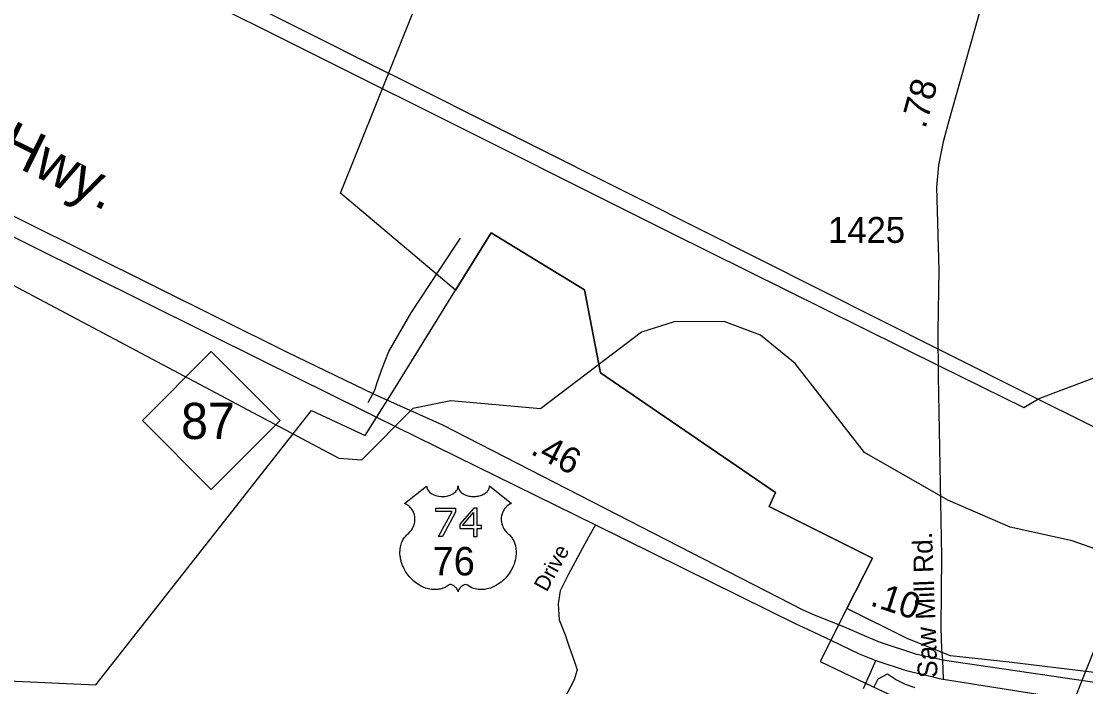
# Model space of a CAD drawing. Extents: x 2225501 to 2309677, y 165449 to 227696.
# Drawn here: x 2252503 to 2257649, y 196661 to 199877 of the extents above; entities that cross this region are included whole.
import ezdxf

# ---------------------------------------------------------------- set-up
doc = ezdxf.new("R2010")
doc.units = 0
for name, color, linetype in [('Black Area Fill Shapes', 7, 'Continuous'), ('E_RDY_CMT_EOP', 7, 'Continuous'), ('MARK ENDS WORD SYMBOL CELL', 7, 'Continuous'), ('Old_Level_3', 7, 'Continuous'), ('Old_Level_33', 7, 'Continuous'), ('Old_Level_46', 7, 'Continuous'), ('P_HYD_Ditch_Flow_Line', 7, 'Continuous'), ('P_HYD_Endwall_838_01_48_Dia_Single_CELL', 7, 'Continuous'), ('P_HYD_Junction_Box_with_Slab_Lid_840_31_15_Dia-Top_CELL', 7, 'Continuous'), ('P_HYD_RipRap_Pad_876_02_18in_Outlet_With_Ditch-Top_CELL', 7, 'Continuous'), ('P_HYD_RipRap_Pad_876_02_18in_Outlet_With_Ditch_CELL', 7, 'Continuous'), ('P_HYD_RipRap_Pad_876_02_24in_Outlet_With_Ditch_CELL', 7, 'Continuous'), ('P_HYD_RipRap_Pad_876_02_36in_Outlet_With_Ditch-Top_CELL', 7, 'Continuous'), ('P_RDY_Dimension_Text', 7, 'Continuous'), ('Prop Support', 7, 'Continuous'), ('Raster_Level_0', 7, 'Continuous'), ('Scratch_Level_2', 7, 'Continuous'), ('Typical Terminator CELL', 7, 'Continuous')]:
    doc.layers.add(name, color=color, linetype=linetype)

msp = doc.modelspace()

# ---------------------------------------------------------------- linework, layer by layer
at = {"layer": 'Black Area Fill Shapes'}
for p, q in [((2254291.9, 199620.2), (2254290.5, 199620.9)), ((2254260.8, 199546.4), (2254361.9, 199495.8)), ((2257417.6, 198050.9), (2256943.1, 198289.2))]:
    msp.add_line(p, q, dxfattribs=at)
for points in [[(2254290.5, 199620.9), (2252914.9, 200311.1), (2250919.7, 201308.6), (2250845.6, 201345.2)], [(2250805.9, 201279), (2252943.9, 200205.6), (2254260.8, 199546.4)], [(2256943.1, 198289.2), (2255486.5, 199020.7), (2254291.9, 199620.2)], [(2254361.9, 199495.8), (2255643.9, 198854.1), (2256944, 198211)], [(2259154.8, 198713.5), (2258436.2, 198435), (2257417.6, 198050.9)], [(2256944, 198211), (2257350, 198010.2), (2257417.6, 198050.9)], [(2259922.2, 196804.3), (2258742.4, 197393.8), (2257417.6, 198050.9)]]:
    msp.add_lwpolyline(points, dxfattribs=at)
at = {"layer": 'Old_Level_3'}
for p, q in [((2254525.6, 198676.1), (2254626.4, 198828.6)), ((2254180, 198034.4), (2254212.4, 198093.9)), ((2254212.4, 198093.9), (2254225.1, 198135.7)), ((2255278.5, 197442.7), (2255246, 197383.3)), ((2255246, 197383.3), (2255216.7, 197329.9)), ((2256606.8, 196725.5), (2256635.4, 196787.9)), ((2256575.3, 196652.4), (2256585.6, 196677.3))]:
    msp.add_line(p, q, dxfattribs=at)
for points in [[(2254225.1, 198135.7), (2254228, 198144.9), (2254245.4, 198191.5), (2254280.3, 198281.7), (2254387.9, 198467.9), (2254525.6, 198676.1)], [(2255216.7, 197329.9), (2255147, 197202.3), (2255108.3, 197124.9), (2255098.6, 197062), (2255103.4, 196984.6), (2255132.4, 196912), (2255151.8, 196853.9), (2255176, 196786.2), (2255190.5, 196742.7), (2255176, 196694.3), (2255127.6, 196602.3), (2255064.7, 196481.4)], [(2256585.6, 196677.3), (2256596.9, 196704.6), (2256606.8, 196725.5)]]:
    msp.add_lwpolyline(points, dxfattribs=at)
at = {"layer": 'Old_Level_33'}
for points in [[(2257406.3, 200835.2), (2257377.1, 200772.2), (2257211.9, 200191.2), (2256987.1, 199395.5), (2256959.8, 199295), (2256937.7, 199182.5), (2256927.5, 199075.2), (2256938.8, 198674.7), (2256934.3, 198380.7), (2256936, 198161.9), (2256951.6, 197291.5), (2256949.8, 196947.1), (2256952.3, 196843.1), (2256956.7, 196790)], [(2256956.7, 196790), (2256960.1, 196697.4)]]:
    msp.add_lwpolyline(points, dxfattribs=at)
at = {"layer": 'Old_Level_46'}
for points in [[(2256956.7, 196790), (2256924.7, 196796.5), (2256832.3, 196817.3), (2256652.3, 196875.8), (2256591.1, 196902.4), (2256480.1, 196951.1), (2256338.5, 197006.2), (2256282.6, 197031), (2254541.8, 197924.5), (2254210.5, 198073.2), (2253786.6, 198278.1), (2252185.6, 199073.8), (2250121.7, 200127.7), (2248768.8, 200789.1), (2247375.2, 201475.6), (2243675.2, 203270.8), (2243284.4, 203458.4), (2243017.1, 203588.4)], [(2242986.4, 203530.7), (2247394.3, 201340.7), (2248933.2, 200581.2), (2250061.9, 200025.4), (2252258.3, 198936.4), (2253668.1, 198237.8), (2254159.3, 197994.4), (2254220.9, 197964), (2255278.5, 197442.7), (2256250.7, 196963.5), (2256279.6, 196949.9), (2256416.4, 196885.1), (2256553.4, 196820.3), (2256635.4, 196787.9), (2256780.8, 196739.2), (2256905.8, 196709.8), (2256941.4, 196700.5), (2256960.1, 196697.4)], [(2260176.7, 196311.4), (2259597.7, 196392.1), (2259295.9, 196446.1), (2256956.7, 196790)], [(2256960.1, 196697.4), (2259291.8, 196328.6), (2260129, 196210.1)]]:
    msp.add_lwpolyline(points, dxfattribs=at)
at = {"layer": 'P_HYD_Ditch_Flow_Line'}
for points in [[(2254602, 197503.9), (2254539.9, 197386.9), (2254520.1, 197386.9), (2254586.1, 197508.2), (2254507.9, 197508.2), (2254507.9, 197524.4), (2254602, 197524.4)], [(2254728.1, 197425.6), (2254728.1, 197440.4), (2254707.6, 197440.4), (2254707.6, 197524.4), (2254690.6, 197524.4), (2254624, 197446.8), (2254624, 197425.6), (2254689.9, 197425.6), (2254689.9, 197386.9), (2254707.6, 197386.9), (2254707.6, 197425.6)], [(2254689.9, 197440.4), (2254636.6, 197440.4), (2254689.9, 197502.5)]]:
    msp.add_lwpolyline(points, close=True, dxfattribs=at)
at = {"layer": 'P_HYD_Endwall_838_01_48_Dia_Single_CELL'}
for points in [[(2254602.2, 198577.4), (2254045.8, 199046.2), (2254853.5, 201059.1)], [(2262842.5, 200192.5), (2261366.2, 197772.7), (2261577, 197677.7), (2260763, 196442.2), (2260802.2, 196384.7), (2260862.2, 196311.2), (2260865.8, 196276.6), (2260817.5, 196273.6), (2260687.2, 196340.6), (2260589.5, 196380.7), (2260484.8, 196410.3), (2260197, 196442.9), (2259793.2, 196485.6), (2259224.8, 196551.9), (2258394, 196652.1), (2257678.2, 196731.8), (2257280, 196779.1), (2256995.8, 196809.4), (2256790.2, 196891.6), (2256494.5, 197038.7)], [(2254602.2, 198577.4), (2254774.2, 198855.3), (2255225.8, 198578.8), (2255303, 198178.2), (2256150, 197600.3), (2256118.8, 197532.2), (2256618.2, 197283), (2256494.5, 197038.7)], [(2256494.5, 197038.7), (2256618.2, 197283), (2256118.8, 197532.2), (2256150, 197600.3), (2255303, 198178.2), (2255225.8, 198578.8), (2254774.2, 198855.3), (2254602.2, 198577.4)], [(2251977.8, 196710.8), (2252864.2, 196669.4), (2253906.2, 197995.3), (2254165.5, 197874.8), (2254302, 198092.7), (2254602.2, 198577.4)], [(2256494.5, 197038.7), (2256364.8, 196783), (2256585.5, 196677.3), (2256673, 196635.5), (2257043.5, 196469), (2257338.8, 196340.6), (2257312.8, 196291), (2257293.5, 196254.1), (2256809.5, 195327.1), (2256412.5, 194566.7), (2256138.2, 194034.5), (2255283, 194024), (2255235, 194023.4), (2255283, 194408), (2254952, 193845.2), (2254422.2, 193712.7), (2253942.2, 193812), (2253061.8, 194329), (2252072.5, 194910)]]:
    msp.add_lwpolyline(points, dxfattribs=at)
at = {"layer": 'P_HYD_Junction_Box_with_Slab_Lid_840_31_15_Dia-Top_CELL'}
for p, q in [((2253088.4, 197947.8), (2253421.4, 198280.8)), ((2253421.4, 198280.8), (2253754.4, 197947.8)), ((2253421.4, 197614.8), (2253088.4, 197947.8)), ((2253754.4, 197947.8), (2253421.4, 197614.8))]:
    msp.add_line(p, q, dxfattribs=at)
at = {"layer": 'P_HYD_RipRap_Pad_876_02_18in_Outlet_With_Ditch-Top_CELL'}
for p, q in [((2254356.5, 197546.3), (2254462.7, 197631)), ((2254462.7, 197631), (2254463, 197626.6)), ((2254463, 197626.6), (2254464.1, 197621.3)), ((2254614.4, 197625.3), (2254614.8, 197631.2)), ((2254614.8, 197631.2), (2254615.2, 197626.2)), ((2254615.2, 197626.2), (2254615.7, 197623.2)), ((2254766.3, 197624.4), (2254766.8, 197628.1)), ((2254766.8, 197628.1), (2254766.9, 197631.3)), ((2254766.9, 197631.3), (2254873.2, 197546.6)), ((2254464.1, 197621.3), (2254464.9, 197618.6)), ((2254464.9, 197618.6), (2254467.4, 197613.5)), ((2254467.4, 197613.5), (2254471.4, 197607.4)), ((2254471.4, 197607.4), (2254477, 197601.4)), ((2254477, 197601.4), (2254483.3, 197596.2)), ((2254483.3, 197596.2), (2254487.6, 197593.5)), ((2254487.6, 197593.5), (2254494.8, 197589.6)), ((2254494.8, 197589.6), (2254503.1, 197586.1)), ((2254503.1, 197586.1), (2254512.2, 197583.5)), ((2254512.2, 197583.5), (2254521.6, 197581.6)), ((2254521.6, 197581.6), (2254531.8, 197580.5)), ((2254531.8, 197580.5), (2254541.9, 197580.3)), ((2254541.9, 197580.3), (2254552.8, 197581.1)), ((2254552.8, 197581.1), (2254564.9, 197583.4)), ((2254564.9, 197583.4), (2254570.5, 197584.9)), ((2254570.5, 197584.9), (2254576.7, 197587)), ((2254576.7, 197587), (2254582.5, 197589.4)), ((2254582.5, 197589.4), (2254588.8, 197592.8)), ((2254588.8, 197592.8), (2254593.9, 197596)), ((2254593.9, 197596), (2254597.9, 197598.9)), ((2254597.9, 197598.9), (2254603.5, 197604.3)), ((2254603.5, 197604.3), (2254608, 197609.9)), ((2254608, 197609.9), (2254609.9, 197613)), ((2254609.9, 197613), (2254611.5, 197616.1)), ((2254611.5, 197616.1), (2254613.8, 197622.5)), ((2254613.8, 197622.5), (2254614.4, 197625.3)), ((2254615.7, 197623.2), (2254616.5, 197620.1)), ((2254616.5, 197620.1), (2254617.8, 197616.9)), ((2254617.8, 197616.9), (2254620, 197612.4)), ((2254620, 197612.4), (2254622.5, 197608.7)), ((2254622.5, 197608.7), (2254627.3, 197603.1)), ((2254627.3, 197603.1), (2254630.2, 197600.3)), ((2254630.2, 197600.3), (2254632.9, 197598.1)), ((2254632.9, 197598.1), (2254640.2, 197593.1)), ((2254640.2, 197593.1), (2254648.6, 197588.9)), ((2254648.6, 197588.9), (2254652.7, 197587.1)), ((2254652.7, 197587.1), (2254657, 197585.5)), ((2254657, 197585.5), (2254662.4, 197583.9)), ((2254662.4, 197583.9), (2254668, 197582.6)), ((2254668, 197582.6), (2254673.5, 197581.6)), ((2254673.5, 197581.6), (2254679.2, 197580.8)), ((2254679.2, 197580.8), (2254684.9, 197580.4)), ((2254684.9, 197580.4), (2254689.6, 197580.3)), ((2254689.6, 197580.3), (2254695.4, 197580.3)), ((2254695.4, 197580.3), (2254700.8, 197580.6)), ((2254700.8, 197580.6), (2254706.2, 197581.3)), ((2254706.2, 197581.3), (2254712.2, 197582.3)), ((2254712.2, 197582.3), (2254717.1, 197583.3)), ((2254717.1, 197583.3), (2254723.5, 197585)), ((2254723.5, 197585), (2254729.3, 197587.1)), ((2254729.3, 197587.1), (2254734.3, 197589.3)), ((2254734.3, 197589.3), (2254740.9, 197592.8)), ((2254740.9, 197592.8), (2254746.3, 197596.1)), ((2254746.3, 197596.1), (2254750.2, 197599.2)), ((2254750.2, 197599.2), (2254754.8, 197603.5)), ((2254754.8, 197603.5), (2254759.2, 197608.6)), ((2254759.2, 197608.6), (2254761.8, 197612.3)), ((2254761.8, 197612.3), (2254763.6, 197616.1)), ((2254763.6, 197616.1), (2254765.3, 197620.1)), ((2254765.3, 197620.1), (2254766.3, 197624.4)), ((2254359.8, 197545), (2254356.5, 197546.3)), ((2254365, 197542.4), (2254359.8, 197545)), ((2254370.4, 197539.1), (2254365, 197542.4)), ((2254374.7, 197536.1), (2254370.4, 197539.1)), ((2254379.2, 197532.5), (2254374.7, 197536.1)), ((2254383.9, 197527.8), (2254379.2, 197532.5)), ((2254388.6, 197522.6), (2254383.9, 197527.8)), ((2254841.3, 197523.1), (2254838.2, 197518.8)), ((2254843.9, 197526.1), (2254841.3, 197523.1)), ((2254846.8, 197529.2), (2254843.9, 197526.1)), ((2254849.9, 197532.2), (2254846.8, 197529.2)), ((2254853, 197535), (2254849.9, 197532.2)), ((2254860.3, 197540.1), (2254853, 197535)), ((2254864.9, 197542.8), (2254860.3, 197540.1)), ((2254870.7, 197545.7), (2254864.9, 197542.8)), ((2254873.2, 197546.6), (2254870.7, 197545.7)), ((2254393.1, 197516.1), (2254388.6, 197522.6)), ((2254397.2, 197509.1), (2254393.1, 197516.1)), ((2254399.6, 197504), (2254397.2, 197509.1)), ((2254402.2, 197496.9), (2254399.6, 197504)), ((2254403.9, 197490.8), (2254402.2, 197496.9)), ((2254405.3, 197483.7), (2254403.9, 197490.8)), ((2254406.1, 197476.4), (2254405.3, 197483.7)), ((2254406.3, 197470.1), (2254406.1, 197476.4)), ((2254823.7, 197477.8), (2254823.4, 197473.3)), ((2254823.4, 197473.3), (2254823.4, 197468.8)), ((2254825, 197487.3), (2254823.7, 197477.8)), ((2254826, 197491.8), (2254825, 197487.3)), ((2254827.5, 197497.2), (2254826, 197491.8)), ((2254830.8, 197505.8), (2254827.5, 197497.2)), ((2254832.8, 197509.9), (2254830.8, 197505.8)), ((2254835.5, 197514.6), (2254832.8, 197509.9)), ((2254838.2, 197518.8), (2254835.5, 197514.6)), ((2254389.5, 197418), (2254392.6, 197422.7)), ((2254392.6, 197422.7), (2254395, 197426.9)), ((2254395, 197426.9), (2254398.3, 197433.1)), ((2254398.3, 197433.1), (2254400.2, 197437.8)), ((2254400.2, 197437.8), (2254402.7, 197444.9)), ((2254402.7, 197444.9), (2254403.9, 197450)), ((2254403.9, 197450), (2254405.1, 197456.4)), ((2254405.1, 197456.4), (2254405.9, 197462.5)), ((2254405.9, 197462.5), (2254406.3, 197470.1)), ((2254823.4, 197468.8), (2254823.7, 197464.1)), ((2254823.7, 197464.1), (2254824.1, 197459.6)), ((2254824.1, 197459.6), (2254824.9, 197454.9)), ((2254824.9, 197454.9), (2254825.7, 197450.7)), ((2254825.7, 197450.7), (2254827, 197445.6)), ((2254827, 197445.6), (2254828.9, 197439.7)), ((2254828.9, 197439.7), (2254831.2, 197434)), ((2254831.2, 197434), (2254836, 197424.8)), ((2254836, 197424.8), (2254842.3, 197415.4)), ((2254344.8, 197363.2), (2254348.3, 197370.3)), ((2254348.3, 197370.3), (2254351.7, 197376.1)), ((2254351.7, 197376.1), (2254355.9, 197382.4)), ((2254355.9, 197382.4), (2254360, 197387.7)), ((2254360, 197387.7), (2254365.5, 197393.6)), ((2254365.5, 197393.6), (2254371.1, 197399)), ((2254371.1, 197399), (2254376.3, 197403.2)), ((2254376.3, 197403.2), (2254382.4, 197409.3)), ((2254382.4, 197409.3), (2254385.6, 197412.9)), ((2254385.6, 197412.9), (2254389.5, 197418)), ((2254842.3, 197415.4), (2254846.7, 197410.1)), ((2254846.7, 197410.1), (2254851.1, 197405.6)), ((2254851.1, 197405.6), (2254857.7, 197400)), ((2254857.7, 197400), (2254861.2, 197396.9)), ((2254861.2, 197396.9), (2254865.3, 197392.8)), ((2254865.3, 197392.8), (2254872, 197385.1)), ((2254872, 197385.1), (2254874.7, 197381.4)), ((2254874.7, 197381.4), (2254877.4, 197377.4)), ((2254877.4, 197377.4), (2254879.9, 197373.2)), ((2254879.9, 197373.2), (2254882.4, 197368.6)), ((2254882.4, 197368.6), (2254884.4, 197364.7)), ((2254333.9, 197311.8), (2254334.1, 197319)), ((2254334.1, 197319), (2254334.9, 197327.3)), ((2254334.9, 197327.3), (2254336.3, 197336.2)), ((2254336.3, 197336.2), (2254338, 197343.8)), ((2254338, 197343.8), (2254339.6, 197349.2)), ((2254339.6, 197349.2), (2254341.8, 197355.9)), ((2254341.8, 197355.9), (2254344.8, 197363.2)), ((2254884.4, 197364.7), (2254888.2, 197355.6)), ((2254888.2, 197355.6), (2254890.9, 197346.7)), ((2254890.9, 197346.7), (2254892.2, 197342.1)), ((2254892.2, 197342.1), (2254894.1, 197331.6)), ((2254894.1, 197331.6), (2254894.9, 197326.5)), ((2254894.9, 197326.5), (2254895.7, 197316.3)), ((2254334, 197303.2), (2254333.9, 197311.8)), ((2254334.7, 197293.8), (2254334, 197303.2)), ((2254335.9, 197285), (2254334.7, 197293.8)), ((2254337.1, 197278.5), (2254335.9, 197285)), ((2254339.1, 197269.4), (2254337.1, 197278.5)), ((2254340.5, 197264.2), (2254339.1, 197269.4)), ((2254890.8, 197270.5), (2254888, 197261.1)), ((2254892.6, 197278.7), (2254890.8, 197270.5)), ((2254894.8, 197292.3), (2254892.6, 197278.7)), ((2254895.7, 197304), (2254894.8, 197292.3)), ((2254895.7, 197316.3), (2254895.7, 197304)), ((2254343.1, 197256), (2254340.5, 197264.2)), ((2254346.3, 197247.4), (2254343.1, 197256)), ((2254350.3, 197238), (2254346.3, 197247.4)), ((2254353.4, 197231.5), (2254350.3, 197238)), ((2254359.1, 197221.2), (2254353.4, 197231.5)), ((2254362.9, 197214.8), (2254359.1, 197221.2)), ((2254368.9, 197206.1), (2254362.9, 197214.8)), ((2254866.7, 197215.4), (2254862.3, 197208.7)), ((2254870.5, 197221.6), (2254866.7, 197215.4)), ((2254876.1, 197231.9), (2254870.5, 197221.6)), ((2254880.4, 197240.7), (2254876.1, 197231.9)), ((2254885.3, 197252.8), (2254880.4, 197240.7)), ((2254888, 197261.1), (2254885.3, 197252.8)), ((2254378.2, 197194.1), (2254368.9, 197206.1)), ((2254384.2, 197187.3), (2254378.2, 197194.1)), ((2254394.3, 197177), (2254384.2, 197187.3)), ((2254401.1, 197170.8), (2254394.3, 197177)), ((2254410.5, 197163.2), (2254401.1, 197170.8)), ((2254423, 197154.6), (2254410.5, 197163.2)), ((2254822.6, 197166.4), (2254815.5, 197161)), ((2254827.7, 197170.6), (2254822.6, 197166.4)), ((2254836, 197178), (2254827.7, 197170.6)), ((2254842.3, 197184.3), (2254836, 197178)), ((2254850.1, 197192.9), (2254842.3, 197184.3)), ((2254856.7, 197201.1), (2254850.1, 197192.9)), ((2254862.3, 197208.7), (2254856.7, 197201.1)), ((2254433.6, 197148.5), (2254423, 197154.6)), ((2254440.3, 197145.1), (2254433.6, 197148.5)), ((2254449.9, 197140.9), (2254440.3, 197145.1)), ((2254457.7, 197137.9), (2254449.9, 197140.9)), ((2254464.9, 197135.6), (2254457.7, 197137.9)), ((2254471.9, 197133.8), (2254464.9, 197135.6)), ((2254478.6, 197132.3), (2254471.9, 197133.8)), ((2254486.6, 197131.1), (2254478.6, 197132.3)), ((2254493.1, 197130.5), (2254486.6, 197131.1)), ((2254498.6, 197130.1), (2254493.1, 197130.5)), ((2254504.6, 197130), (2254498.6, 197130.1)), ((2254510.3, 197130.2), (2254504.6, 197130)), ((2254516.7, 197130.8), (2254510.3, 197130.2)), ((2254522.6, 197131.7), (2254516.7, 197130.8)), ((2254529.3, 197133), (2254522.6, 197131.7)), ((2254535.8, 197134.7), (2254529.3, 197133)), ((2254541.8, 197136.7), (2254535.8, 197134.7)), ((2254547, 197138.7), (2254541.8, 197136.7)), ((2254551.3, 197140.7), (2254547, 197138.7)), ((2254557.2, 197143.9), (2254551.3, 197140.7)), ((2254562.2, 197147), (2254557.2, 197143.9)), ((2254566.7, 197150.1), (2254562.2, 197147)), ((2254571.5, 197153.6), (2254566.7, 197150.1)), ((2254575.1, 197154.4), (2254571.5, 197153.6)), ((2254577.6, 197154.4), (2254575.1, 197154.4)), ((2254580.8, 197154.2), (2254577.6, 197154.4)), ((2254584.6, 197153.2), (2254580.8, 197154.2)), ((2254587.7, 197152), (2254584.6, 197153.2)), ((2254591.2, 197150.3), (2254587.7, 197152)), ((2254595.4, 197147.7), (2254591.2, 197150.3)), ((2254599.5, 197144.4), (2254595.4, 197147.7)), ((2254602.8, 197141.2), (2254599.5, 197144.4)), ((2254606.5, 197137), (2254602.8, 197141.2)), ((2254608.8, 197133.6), (2254606.5, 197137)), ((2254611.1, 197129.9), (2254608.8, 197133.6)), ((2254613, 197125.5), (2254611.1, 197129.9)), ((2254614.7, 197118.8), (2254613, 197125.5)), ((2254615.9, 197124.1), (2254614.7, 197118.8)), ((2254617.3, 197127.7), (2254615.9, 197124.1)), ((2254618.6, 197130.4), (2254617.3, 197127.7)), ((2254622.3, 197136.3), (2254618.6, 197130.4)), ((2254624.2, 197138.5), (2254622.3, 197136.3)), ((2254626.8, 197141.4), (2254624.2, 197138.5)), ((2254630.4, 197144.9), (2254626.8, 197141.4)), ((2254633.4, 197147.3), (2254630.4, 197144.9)), ((2254637.3, 197149.8), (2254633.4, 197147.3)), ((2254640.3, 197151.4), (2254637.3, 197149.8)), ((2254645.2, 197153.4), (2254640.3, 197151.4)), ((2254649.9, 197154.4), (2254645.2, 197153.4)), ((2254655, 197154.1), (2254649.9, 197154.4)), ((2254657.2, 197153.5), (2254655, 197154.1)), ((2254661, 197151.5), (2254657.2, 197153.5)), ((2254674.1, 197143.2), (2254661, 197151.5)), ((2254681.9, 197139.4), (2254674.1, 197143.2)), ((2254689.6, 197136.4), (2254681.9, 197139.4)), ((2254698.1, 197133.9), (2254689.6, 197136.4)), ((2254706.2, 197132.2), (2254698.1, 197133.9)), ((2254713.9, 197131.1), (2254706.2, 197132.2)), ((2254722.2, 197130.4), (2254713.9, 197131.1)), ((2254730.4, 197130.4), (2254722.2, 197130.4)), ((2254736.6, 197130.8), (2254730.4, 197130.4)), ((2254742.9, 197131.4), (2254736.6, 197130.8)), ((2254749.7, 197132.4), (2254742.9, 197131.4)), ((2254755.4, 197133.6), (2254749.7, 197132.4)), ((2254771.1, 197138), (2254755.4, 197133.6)), ((2254780.5, 197141.6), (2254771.1, 197138)), ((2254787.8, 197144.7), (2254780.5, 197141.6)), ((2254796, 197148.9), (2254787.8, 197144.7)), ((2254805.7, 197154.5), (2254796, 197148.9)), ((2254815.5, 197161), (2254805.7, 197154.5))]:
    msp.add_line(p, q, dxfattribs=at)
at = {"layer": 'P_HYD_RipRap_Pad_876_02_36in_Outlet_With_Ditch-Top_CELL'}
for points in [[(2254602.2, 198577.4), (2254045.8, 199046.2), (2254853.5, 201059.1)], [(2262842.5, 200192.5), (2261366.2, 197772.7), (2261577, 197677.7), (2260763, 196442.2), (2260802.2, 196384.7), (2260862.2, 196311.2), (2260865.8, 196276.6), (2260817.5, 196273.6), (2260687.2, 196340.6), (2260589.5, 196380.7), (2260484.8, 196410.3), (2260197, 196442.9), (2259793.2, 196485.6), (2259224.8, 196551.9), (2258394, 196652.1), (2257678.2, 196731.8), (2257280, 196779.1), (2256995.8, 196809.4), (2256790.2, 196891.6), (2256494.5, 197038.7)], [(2254602.2, 198577.4), (2254774.2, 198855.3), (2255225.8, 198578.8), (2255303, 198178.2), (2256150, 197600.3), (2256118.8, 197532.2), (2256618.2, 197283), (2256494.5, 197038.7)], [(2256494.5, 197038.7), (2256618.2, 197283), (2256118.8, 197532.2), (2256150, 197600.3), (2255303, 198178.2), (2255225.8, 198578.8), (2254774.2, 198855.3), (2254602.2, 198577.4)], [(2251977.8, 196710.8), (2252864.2, 196669.4), (2253906.2, 197995.3), (2254165.5, 197874.8), (2254302, 198092.7), (2254602.2, 198577.4)], [(2256494.5, 197038.7), (2256364.8, 196783), (2256585.5, 196677.3), (2256673, 196635.5), (2257043.5, 196469), (2257338.8, 196340.6), (2257312.8, 196291), (2257293.5, 196254.1), (2256809.5, 195327.1), (2256412.5, 194566.7), (2256138.2, 194034.5), (2255283, 194024), (2255235, 194023.4), (2255283, 194408), (2254952, 193845.2), (2254422.2, 193712.7), (2253942.2, 193812), (2253061.8, 194329), (2252072.5, 194910)]]:
    msp.add_lwpolyline(points, dxfattribs=at)
at = {"layer": 'Prop Support'}
msp.add_lwpolyline([(2257976.7, 197228), (2257584.7, 197366.8), (2257283.7, 197431.8), (2256982.6, 197562.3), (2256580.7, 197793.2), (2256244.7, 198222.8), (2256076.7, 198360.5), (2255901.6, 198426.3), (2255659.7, 198424.5), (2255501.8, 198375), (2255013.7, 198004.1), (2254579.6, 198042), (2254396.7, 198006.2), (2254148.6, 197755.2), (2254040.6, 197763.9), (2251865.6, 198918.2), (2251519.7, 199088.4)], dxfattribs=at)
at = {"layer": 'Typical Terminator CELL'}
for points in [[(2257554.7, 196498.2), (2257688.6, 196833.4), (2257936.8, 197068.1), (2257976.7, 197228)], [(2256624.4, 196656.8), (2256645.7, 196699.1), (2256691.5, 196723.7), (2256733.9, 196694.2), (2256776.2, 196672.6), (2256822.5, 196657.1)]]:
    msp.add_lwpolyline(points, dxfattribs=at)

# ---------------------------------------------------------------- texts
at = {"layer": 'E_RDY_CMT_EOP'}
msp.add_text('1425', height=125, dxfattribs=at).set_placement((2256404.1, 198806.3))
at = {"layer": 'MARK ENDS WORD SYMBOL CELL'}
msp.add_text('Saw Mill Rd.', height=95, rotation=92.2178, dxfattribs=at).set_placement((2256933.5, 196704.9))
at = {"layer": 'P_HYD_Ditch_Flow_Line'}
msp.add_text('76', height=137.5, dxfattribs=at).set_placement((2254491.5, 197198.9))
at = {"layer": 'P_HYD_RipRap_Pad_876_02_18in_Outlet_With_Ditch_CELL'}
msp.add_text('87', height=175, dxfattribs=at).set_placement((2253275.6, 197858.1))
at = {"layer": 'P_HYD_RipRap_Pad_876_02_24in_Outlet_With_Ditch_CELL'}
msp.add_text('Drive', height=75, rotation=61.3254, dxfattribs=at).set_placement((2255043.4, 197115.4))
at = {"layer": 'P_RDY_Dimension_Text'}
msp.add_text('.78', height=125, rotation=74.8336, dxfattribs=at).set_placement((2256874.1, 199354.4))
at = {"layer": 'Raster_Level_0'}
for s, rotation, p in [('.46', 332.8301, (2254959.9, 197787.9)), ('.10', 341.9796, (2256602.1, 197055.2))]:
    msp.add_text(s, height=125, rotation=rotation, dxfattribs=at).set_placement(p)
at = {"layer": 'Scratch_Level_2'}
msp.add_text('Andrew Jackson Hwy.', height=200, rotation=333.7311, dxfattribs=at).set_placement((2250552.6, 200122.7))

doc.saveas('drawing.dxf')
